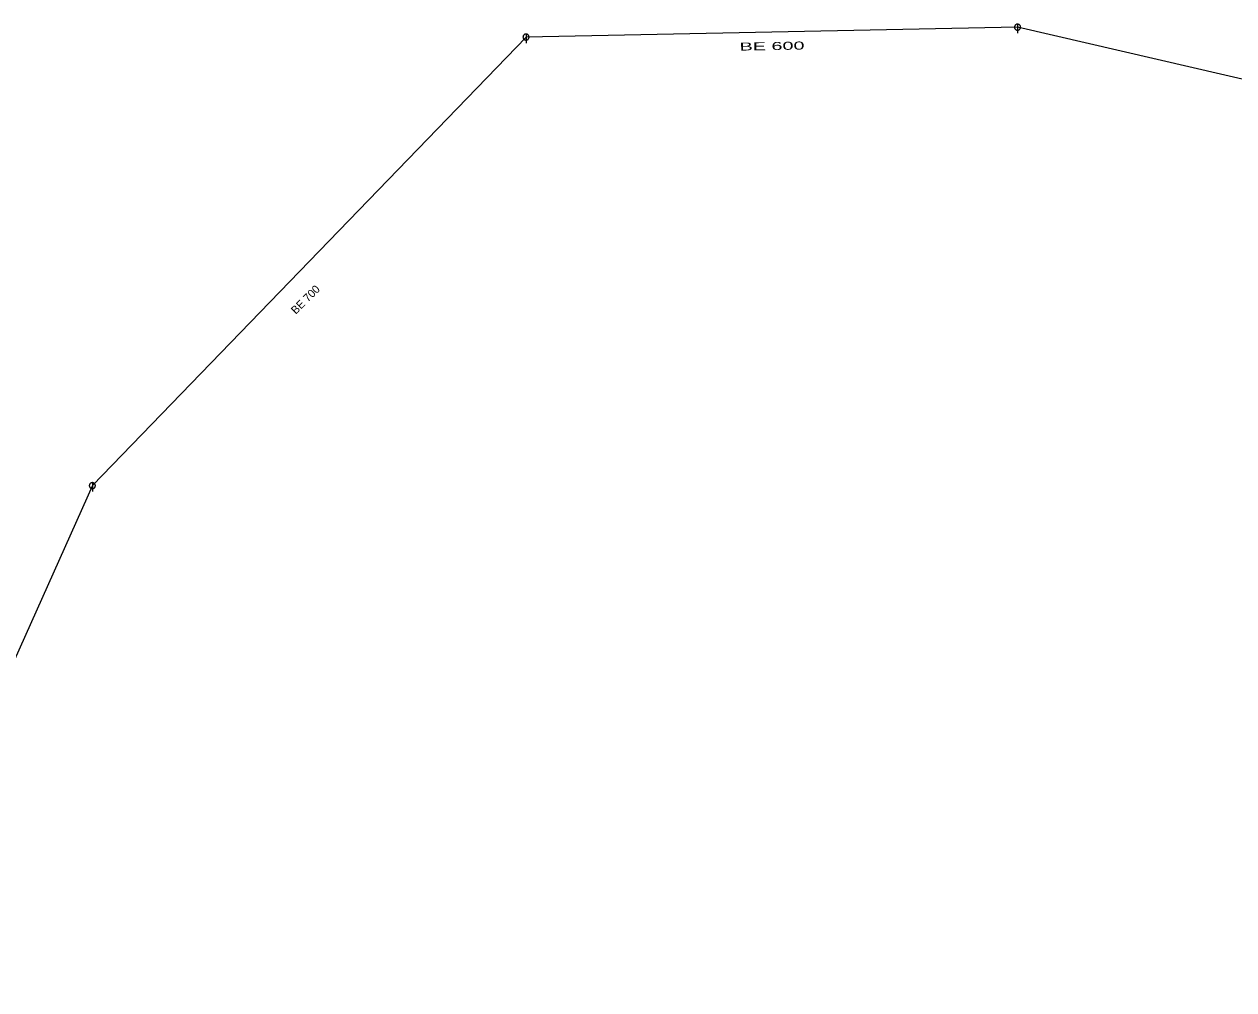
# Model space of a CAD drawing. Extents: x -687468 to -685917, y -974192 to -973456.
# Drawn here: x -686842.6 to -686741.9, y -973963.4 to -973883 of the extents above; entities that cross this region are included whole.
import ezdxf
from ezdxf.enums import TextEntityAlignment as Align

# ---------------------------------------------------------------- set-up
doc = ezdxf.new("R2010")
doc.units = 0
doc.header["$LTSCALE"] = 0.27
for name, color, linetype, lineweight in [('1', 7, 'Continuous', 13), ('14', 7, 'Continuous', 25), ('22', 7, 'Continuous', 13)]:
    doc.layers.add(name, color=color, linetype=linetype, lineweight=lineweight)

msp = doc.modelspace()

# ---------------------------------------------------------------- linework, layer by layer
at = {"layer": '14'}
for p, q in [((-686759.899, -973883.22), (-686800.832, -973884.042)), ((-686710.057, -973894.737), (-686759.899, -973883.22)), ((-686800.831, -973884.042), (-686836.948, -973921.392)), ((-686836.948, -973921.392), (-686855.743, -973963.372))]:
    msp.add_line(p, q, dxfattribs=at)
at = {"layer": '22'}
for p, q in [((-686800.831, -973883.79), (-686800.832, -973884.534)), ((-686759.898, -973882.968), (-686759.899, -973883.712)), ((-686836.947, -973921.14), (-686836.948, -973921.884))]:
    msp.add_line(p, q, dxfattribs=at)
for points in [[(-686800.58, -973884.042), (-686800.581, -973884.016), (-686800.585, -973883.99), (-686800.591, -973883.964), (-686800.601, -973883.94), (-686800.613, -973883.916), (-686800.627, -973883.894), (-686800.644, -973883.873), (-686800.662, -973883.855), (-686800.683, -973883.838), (-686800.705, -973883.824), (-686800.729, -973883.812), (-686800.753, -973883.802), (-686800.779, -973883.796), (-686800.805, -973883.792), (-686800.831, -973883.79), (-686800.857, -973883.791), (-686800.883, -973883.795), (-686800.909, -973883.801), (-686800.934, -973883.811), (-686800.957, -973883.823), (-686800.979, -973883.837), (-686801, -973883.854), (-686801.018, -973883.872), (-686801.035, -973883.893), (-686801.049, -973883.915), (-686801.061, -973883.939), (-686801.071, -973883.963), (-686801.078, -973883.989), (-686801.082, -973884.015), (-686801.084, -973884.041), (-686801.083, -973884.067), (-686801.079, -973884.093), (-686801.072, -973884.119), (-686801.062, -973884.144), (-686801.05, -973884.167), (-686801.036, -973884.189), (-686801.019, -973884.21), (-686801.001, -973884.228), (-686800.98, -973884.245), (-686800.958, -973884.259), (-686800.935, -973884.271), (-686800.91, -973884.281), (-686800.884, -973884.288), (-686800.858, -973884.292), (-686800.832, -973884.294), (-686800.806, -973884.293), (-686800.78, -973884.289), (-686800.754, -973884.282), (-686800.73, -973884.272), (-686800.706, -973884.26), (-686800.684, -973884.246), (-686800.663, -973884.229), (-686800.645, -973884.211), (-686800.628, -973884.19), (-686800.614, -973884.168), (-686800.602, -973884.145), (-686800.592, -973884.12), (-686800.586, -973884.094), (-686800.582, -973884.068)], [(-686759.647, -973883.22), (-686759.648, -973883.194), (-686759.652, -973883.168), (-686759.658, -973883.142), (-686759.668, -973883.118), (-686759.68, -973883.094), (-686759.694, -973883.072), (-686759.711, -973883.051), (-686759.729, -973883.033), (-686759.75, -973883.016), (-686759.772, -973883.002), (-686759.796, -973882.99), (-686759.82, -973882.98), (-686759.846, -973882.974), (-686759.872, -973882.97), (-686759.898, -973882.968), (-686759.924, -973882.969), (-686759.95, -973882.973), (-686759.976, -973882.979), (-686760.001, -973882.989), (-686760.024, -973883.001), (-686760.046, -973883.015), (-686760.067, -973883.032), (-686760.085, -973883.05), (-686760.102, -973883.071), (-686760.116, -973883.093), (-686760.128, -973883.117), (-686760.138, -973883.141), (-686760.145, -973883.167), (-686760.149, -973883.193), (-686760.151, -973883.219), (-686760.15, -973883.245), (-686760.146, -973883.271), (-686760.139, -973883.297), (-686760.129, -973883.322), (-686760.117, -973883.345), (-686760.103, -973883.367), (-686760.086, -973883.388), (-686760.068, -973883.406), (-686760.047, -973883.423), (-686760.025, -973883.437), (-686760.002, -973883.449), (-686759.977, -973883.459), (-686759.951, -973883.466), (-686759.925, -973883.47), (-686759.899, -973883.472), (-686759.873, -973883.471), (-686759.847, -973883.467), (-686759.821, -973883.46), (-686759.797, -973883.45), (-686759.773, -973883.438), (-686759.751, -973883.424), (-686759.73, -973883.407), (-686759.712, -973883.389), (-686759.695, -973883.368), (-686759.681, -973883.346), (-686759.669, -973883.323), (-686759.659, -973883.298), (-686759.653, -973883.272), (-686759.649, -973883.246)], [(-686836.696, -973921.392), (-686836.697, -973921.366), (-686836.701, -973921.34), (-686836.707, -973921.314), (-686836.717, -973921.29), (-686836.729, -973921.266), (-686836.743, -973921.244), (-686836.76, -973921.223), (-686836.778, -973921.205), (-686836.799, -973921.188), (-686836.821, -973921.174), (-686836.845, -973921.162), (-686836.869, -973921.152), (-686836.895, -973921.146), (-686836.921, -973921.142), (-686836.947, -973921.14), (-686836.973, -973921.141), (-686836.999, -973921.145), (-686837.025, -973921.151), (-686837.05, -973921.161), (-686837.073, -973921.173), (-686837.095, -973921.187), (-686837.116, -973921.204), (-686837.134, -973921.222), (-686837.151, -973921.243), (-686837.165, -973921.265), (-686837.177, -973921.289), (-686837.187, -973921.313), (-686837.194, -973921.339), (-686837.198, -973921.365), (-686837.2, -973921.391), (-686837.199, -973921.417), (-686837.195, -973921.443), (-686837.188, -973921.469), (-686837.178, -973921.494), (-686837.166, -973921.517), (-686837.152, -973921.539), (-686837.135, -973921.56), (-686837.117, -973921.578), (-686837.096, -973921.595), (-686837.074, -973921.609), (-686837.051, -973921.621), (-686837.026, -973921.631), (-686837, -973921.638), (-686836.974, -973921.642), (-686836.948, -973921.644), (-686836.922, -973921.643), (-686836.896, -973921.639), (-686836.87, -973921.632), (-686836.846, -973921.622), (-686836.822, -973921.61), (-686836.8, -973921.596), (-686836.779, -973921.579), (-686836.761, -973921.561), (-686836.744, -973921.54), (-686836.73, -973921.518), (-686836.718, -973921.495), (-686836.708, -973921.47), (-686836.702, -973921.444), (-686836.698, -973921.418)]]:
    msp.add_lwpolyline(points, close=True, dxfattribs=at)

# ---------------------------------------------------------------- texts
at = {"layer": '1', "width": 1.85}
msp.add_text('BE 600', height=0.6667, rotation=1, dxfattribs=at).set_placement((-686780.34, -973885.121), align=Align.CENTER)
at = {"layer": '1'}
msp.add_text('BE 700', height=0.6667, rotation=45, dxfattribs=at).set_placement((-686818.968, -973906.132), align=Align.CENTER)

doc.saveas('drawing.dxf')
